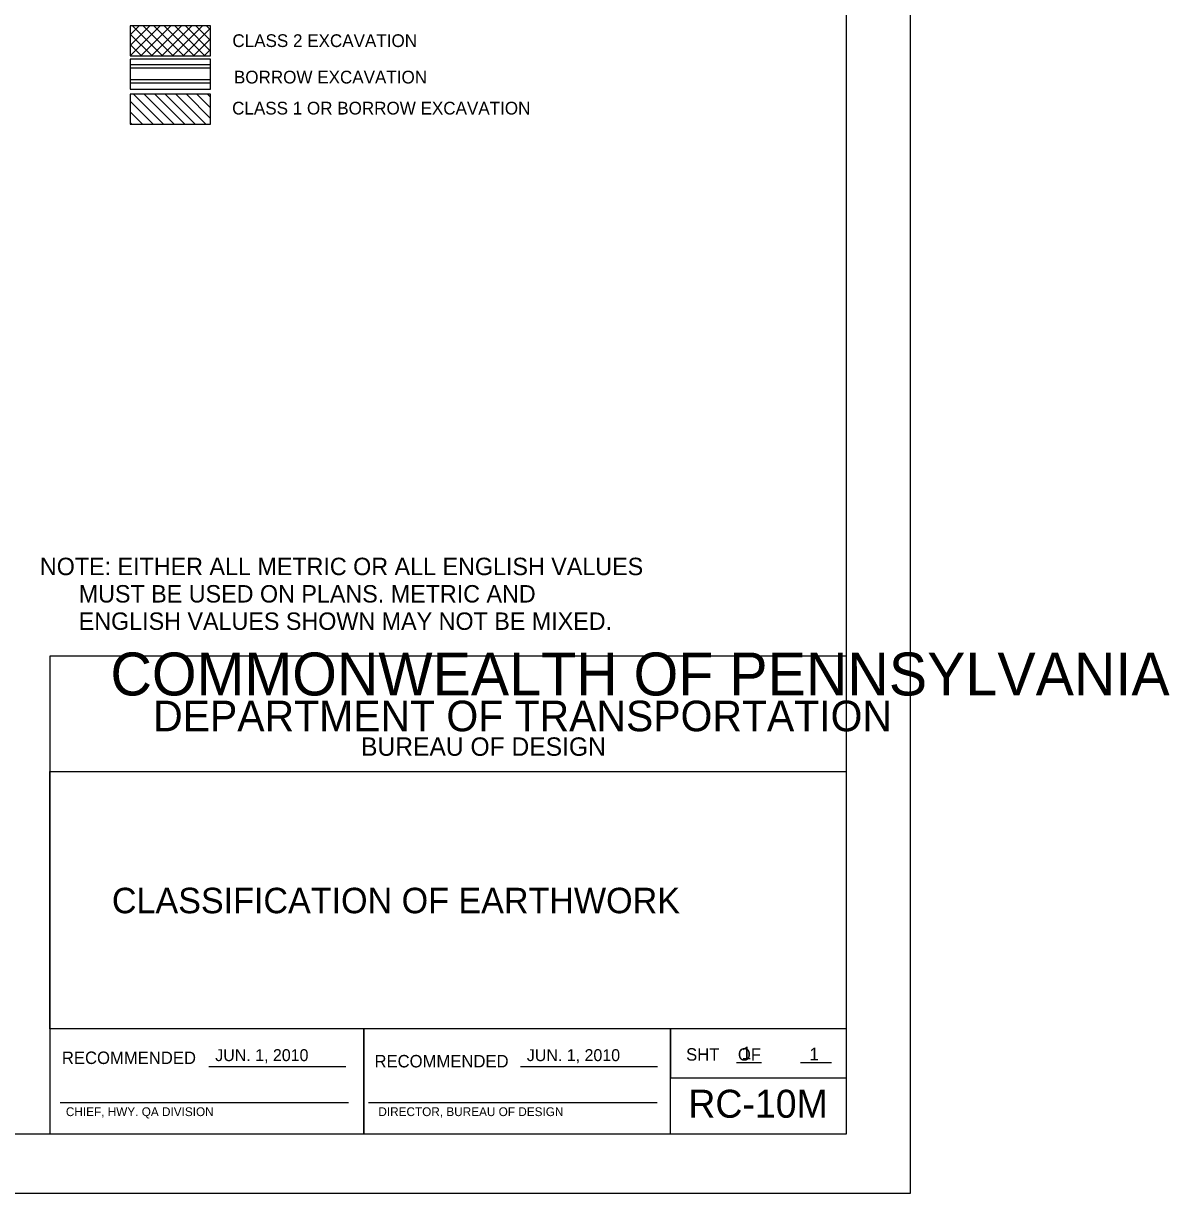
# Model space of a CAD drawing. Extents: x 240 to 1147, y 662 to 1256.
# Drawn here: x 858.8 to 1146.6, y 662 to 956 of the extents above; entities that cross this region are included whole.
import ezdxf

# ---------------------------------------------------------------- set-up
doc = ezdxf.new("R2010")
doc.units = 0
for name, color, linetype in [('1', 7, 'Continuous'), ('2', 7, 'Continuous'), ('3', 7, 'Continuous'), ('PLT-BNDY', 7, 'Continuous')]:
    doc.layers.add(name, color=color, linetype=linetype)

msp = doc.modelspace()

# ---------------------------------------------------------------- linework, layer by layer
at = {"layer": '1'}
for p, q in [((905.33225, 693.958875), (939.77175, 693.958875)), ((983.58425, 693.958875), (1018.00525, 693.958875)), ((1037.853, 694.958875), (1044.09475, 694.958875)), ((1053.92175, 694.958875), (1061.69275, 694.958875)), ((868.03225, 684.900375), (940.44275, 684.900375)), ((945.44275, 684.900375), (1017.94275, 684.900375))]:
    msp.add_line(p, q, dxfattribs=at)
msp.add_lwpolyline([(1065.4425, 677.018625), (1065.4425, 1241.018625), (279.4425, 1241.018625), (279.4425, 677.018625), (1065.4425, 677.018625), (1065.4425, 703.377625), (865.4425, 703.377625), (865.4425, 768.055125), (1065.4425, 768.055125), (1065.4425, 797.018625), (865.4425, 797.018625), (865.4425, 677.018625), (944.244, 677.018625), (944.244, 703.377625), (944.244, 677.018625), (1021.244, 677.018625), (1021.244, 703.377625), (1021.244, 691.061125), (1065.4425, 691.061125)], dxfattribs=at)
at = {"layer": '2'}
for p, q in [((885.600375, 950.48925), (890.494125, 955.38075)), ((885.600375, 953.14125), (887.842125, 955.38075)), ((891.089875, 947.8455), (885.600375, 953.333)), ((885.608625, 947.8455), (893.144125, 955.38075)), ((893.742125, 947.8455), (886.206625, 955.38075)), ((888.260875, 947.8455), (895.796125, 955.38075)), ((896.392125, 947.8455), (888.856625, 955.38075)), ((890.912875, 947.8455), (898.448375, 955.38075)), ((899.044125, 947.8455), (891.508625, 955.38075)), ((893.564875, 947.8455), (901.100375, 955.38075)), ((901.696125, 947.8455), (894.160875, 955.38075)), ((896.214875, 947.8455), (903.750375, 955.38075)), ((904.348375, 947.8455), (896.812875, 955.38075)), ((898.867125, 947.8455), (905.798375, 954.77675)), ((905.798375, 949.0455), (899.462875, 955.38075)), ((905.798375, 951.6975), (902.114875, 955.38075)), ((905.798375, 954.3495), (904.767125, 955.38075)), ((888.437875, 947.8455), (885.600375, 950.68075)), ((901.519125, 947.8455), (905.798375, 952.1245)), ((885.785875, 947.8455), (885.600375, 948.03075)), ((904.171125, 947.8455), (905.798375, 949.4725)), ((885.581625, 945.67175), (905.779625, 945.67175)), ((885.581625, 944.82175), (905.779625, 944.82175)), ((885.581625, 941.92175), (905.779625, 941.92175)), ((885.581625, 941.07175), (905.779625, 941.07175)), ((893.979625, 930.708), (886.444125, 938.24325)), ((896.631625, 930.708), (889.096125, 938.24325)), ((899.283625, 930.708), (891.748375, 938.24325)), ((901.933625, 930.708), (894.398375, 938.24325)), ((904.585875, 930.708), (897.050375, 938.24325)), ((905.800375, 932.1455), (899.702375, 938.24325)), ((905.800375, 934.7975), (902.354625, 938.24325)), ((905.800375, 937.4495), (905.006625, 938.24325)), ((891.327375, 930.708), (885.602375, 936.433)), ((888.677375, 930.708), (885.602375, 933.78075)), ((886.025375, 930.708), (885.602375, 931.13075))]:
    msp.add_line(p, q, dxfattribs=at)
for points in [[(905.798375, 955.38075), (885.600375, 955.38075), (885.600375, 947.8455), (905.798375, 947.8455)], [(905.779625, 947.0205), (885.581625, 947.0205), (885.581625, 939.485), (905.779625, 939.485)], [(905.800375, 938.24325), (885.602375, 938.24325), (885.602375, 930.708), (905.800375, 930.708)]]:
    msp.add_lwpolyline(points, close=True, dxfattribs=at)
at = {"layer": 'PLT-BNDY'}
msp.add_lwpolyline([(240.4425, 1256.018625), (1081.4425, 1256.018625), (1081.4425, 662.018625), (240.4425, 662.018625)], close=True, dxfattribs=at)

# ---------------------------------------------------------------- texts
at = {"layer": '1'}
for s, height, p in [('COMMONWEALTH OF PENNSYLVANIA', 10.7833725, (880.6345, 787.162125)), ('DEPARTMENT OF TRANSPORTATION', 7.6842885, (891.35525, 778.167875)), ('BUREAU OF DESIGN', 4.6220925, (943.56975, 772.005625)), ('CLASSIFICATION OF EARTHWORK', 6.4000005, (881.00225, 732.451875)), ('RECOMMENDED', 3.1259865, (868.44275, 694.573375)), ('JUN. 1, 2010', 3, (906.947276, 695.302218)), ('RECOMMENDED', 3.1259865, (946.94275, 693.723375)), ('JUN. 1, 2010', 3, (985.199276, 695.302218)), ('SHT    OF', 3.126, (1025.19275, 695.423375)), ('1', 3.125987, (1039.19275, 695.773375)), ('1', 3.125, (1056.19275, 695.523375)), ('RC-10M', 7.0324995, (1025.758, 681.076375)), ('CHIEF, HWY. QA DIVISION', 2.2099875, (869.445, 681.487125)), ('DIRECTOR, BUREAU OF DESIGN', 2.2099875, (947.91425, 681.487375))]:
    msp.add_text(s, height=height, dxfattribs=at).set_placement(p)
at = {"layer": '2'}
for s, p in [('NOTE: EITHER ALL METRIC OR ALL ENGLISH VALUES', (862.919875, 817.391)), ('      MUST BE USED ON PLANS. METRIC AND', (862.919875, 810.516)), ('      ENGLISH VALUES SHOWN MAY NOT BE MIXED.', (862.919875, 803.641))]:
    msp.add_text(s, height=4.37499975, dxfattribs=at).set_placement(p)
at = {"layer": '3'}
for s, height, p in [('CLASS 2 EXCAVATION', 3.1999875, (911.256625, 950.06625)), ('BORROW EXCAVATION', 3.1999875, (911.646125, 940.91)), ('CLASS 1 OR BORROW EXCAVATION', 3.1999995, (911.192125, 933.11425))]:
    msp.add_text(s, height=height, dxfattribs=at).set_placement(p)

doc.saveas('drawing.dxf')
